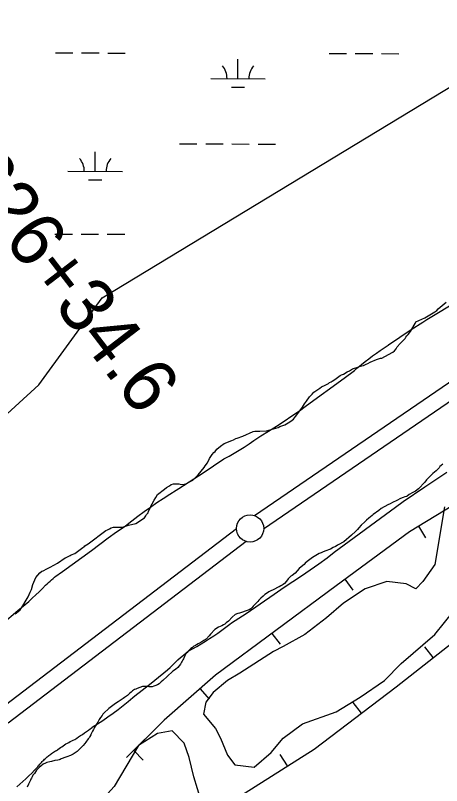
# Model space of a CAD drawing. Extents: x 3177385 to 3215275, y 903885 to 929304.
# Drawn here: x 3193361 to 3194143, y 917073 to 918487 of the extents above; entities that cross this region are included whole.
import ezdxf

# ---------------------------------------------------------------- set-up
doc = ezdxf.new("R2010")
doc.units = 0
for name, color, linetype in [('V-BORW-LINE', 7, 'Continuous'), ('V-LEVE-TOET', 7, 'Continuous'), ('V-SITE-VEGE', 7, 'Continuous'), ('V-SURV-IDEN', 7, 'Continuous'), ('V-SURV-LINE', 7, 'Continuous'), ('V-WETL-SWMP', 7, 'Continuous')]:
    doc.layers.add(name, color=color, linetype=linetype)

msp = doc.modelspace()

# ---------------------------------------------------------------- linework, layer by layer
at = {"layer": 'V-BORW-LINE'}
for p, q in [((3194100.3, 917548.6), (3194113.3, 917527.2)), ((3193965.2, 917451.3), (3193980, 917431.2)), ((3193831.4, 917352), (3193846.3, 917331.9)), ((3194127.2, 917307.4), (3194111.8, 917327)), ((3193699.6, 917250.2), (3193716.1, 917231.4)), ((3193995.5, 917205.4), (3193980.4, 917225.3)), ((3193577.9, 917136.7), (3193595.6, 917119)), ((3193860.1, 917108.6), (3193846.7, 917129.8))]:
    msp.add_line(p, q, dxfattribs=at)
for points in [[(3194274, 917653.9), (3194083.8, 917538.6)], [(3194083.8, 917538.6), (3193949.2, 917439.5)], [(3193949.2, 917439.5), (3193728.2, 917275.3)], [(3194059, 917253.6), (3194170.6, 917341.5)], [(3193728.2, 917275.3), (3193633.6, 917192.4)], [(3193909, 917139.6), (3194059, 917253.6)], [(3193633.6, 917192.4), (3193565, 917123.8)], [(3193633.6, 917192.4), (3193579, 917137.7)], [(3193770.6, 917052.1), (3193909, 917139.6)]]:
    msp.add_lwpolyline(points, dxfattribs=at)
at = {"layer": 'V-LEVE-TOET'}
for points in [[(3193416.5, 917440.6), (3193419.2, 917443.1), (3193421.8, 917445.6), (3193424.6, 917448.1), (3193427.3, 917450.5), (3193430.1, 917452.8), (3193433, 917455.1), (3193435.8, 917457.4), (3193438.8, 917459.6), (3193441.7, 917461.7), (3193444.7, 917463.8), (3193447.1, 917465.4), (3193447.1, 917465.4), (3193500.4, 917504.3), (3193500.4, 917504.3), (3193515.6, 917515.9), (3193531, 917527.2), (3193546.5, 917538.3), (3193562.3, 917549.1), (3193563.2, 917549.6), (3193563.2, 917549.6), (3193574.3, 917558.5), (3193585.6, 917567.1), (3193597, 917575.6), (3193608.5, 917583.9), (3193620.2, 917592), (3193632.1, 917599.8), (3193644, 917607.5), (3193656.1, 917614.9), (3193660.7, 917617.7), (3193660.7, 917617.7), (3193705.4, 917646.8), (3193743.4, 917672.4), (3193743.4, 917672.4), (3193752.8, 917677.5), (3193762.2, 917682.9), (3193771.4, 917688.4), (3193780.5, 917694), (3193789.5, 917699.9), (3193798.5, 917705.8), (3193807.3, 917712), (3193811, 917714.6), (3193825.4, 917723.4), (3193839.7, 917732.4), (3193853.9, 917741.6), (3193868, 917751.1), (3193881.8, 917760.7), (3193895, 917770.3), (3193963.8, 917820.7), (3193982.6, 917834.4), (3193989.1, 917840), (3193995.7, 917845.5), (3194002.4, 917851), (3194009.2, 917856.3), (3194016.1, 917861.5), (3194023.1, 917866.6), (3194030.1, 917871.5), (3194037.2, 917876.4), (3194044.5, 917881.1), (3194045, 917881.5), (3194065.8, 917895.9), (3194086.8, 917909.9), (3194108.1, 917923.6), (3194115.8, 917928.4), (3194115.8, 917928.4), (3194175.4, 917964.6)], [(3193441.1, 917140.4), (3193443.6, 917142.2), (3193446.1, 917143.9), (3193448.6, 917145.6), (3193451.2, 917147.3), (3193453.7, 917148.9), (3193456.4, 917150.4), (3193459, 917151.9), (3193461.7, 917153.4), (3193464.4, 917154.8), (3193467.1, 917156.1), (3193469.7, 917157.4), (3193473.4, 917159.6), (3193477, 917161.9), (3193480.6, 917164.3), (3193484.2, 917166.6), (3193487.8, 917169.1), (3193491.3, 917171.6), (3193494.8, 917174.1), (3193498.2, 917176.7), (3193501.6, 917179.4), (3193501.7, 917179.5), (3193511.5, 917185.8), (3193521.1, 917192.2), (3193530.7, 917198.8), (3193540.1, 917205.6), (3193549.4, 917212.5), (3193558.6, 917219.6), (3193567.6, 917226.8), (3193576.6, 917234.3), (3193580.1, 917237.3), (3193580.1, 917237.3), (3193607, 917258.1), (3193633.5, 917279.3), (3193640.2, 917284.8), (3193640.2, 917284.8), (3193644.8, 917289.5), (3193649.5, 917294.2), (3193654.2, 917298.8), (3193659.1, 917303.3), (3193664, 917307.7), (3193669, 917312), (3193674.1, 917316.3), (3193677.8, 917319.2), (3193677.8, 917319.2), (3193685.8, 917323.6), (3193693.7, 917328.1), (3193701.6, 917332.7), (3193709.4, 917337.5), (3193717, 917342.4), (3193724.7, 917347.4), (3193732.2, 917352.6), (3193739.6, 917357.9), (3193746.9, 917363.3), (3193754.2, 917368.9), (3193757.6, 917371.5), (3193757.6, 917371.5), (3193783.9, 917388.5), (3193809.9, 917406), (3193835.7, 917423.9), (3193853.7, 917436.8), (3193853.7, 917436.8), (3193869.9, 917447.1), (3193885.9, 917457.6), (3193901.8, 917468.4), (3193917.4, 917479.5), (3193932.8, 917490.9), (3193945.8, 917500.8), (3193945.8, 917500.8), (3194058.2, 917583.8), (3194072, 917594.2), (3194072, 917594.2), (3194112, 917621.2), (3194152.3, 917647.8)], [(3193336.9, 917369.6), (3193365.5, 917394.1), (3193365.5, 917394.1), (3193372.2, 917399.6), (3193378.9, 917405.1), (3193385.4, 917410.8), (3193391.9, 917416.6), (3193398.2, 917422.5), (3193404.5, 917428.5), (3193410.6, 917434.6), (3193416.5, 917440.6)], [(3193363.7, 917070.3), (3193369.3, 917075.1), (3193374.9, 917080.1), (3193380.3, 917085.1), (3193385.7, 917090.2), (3193391, 917095.4), (3193396.2, 917100.7), (3193401.3, 917106.1), (3193402, 917106.9), (3193403.3, 917108.6), (3193404.6, 917110.2), (3193406, 917111.8), (3193407.4, 917113.4), (3193408.8, 917114.9), (3193410.2, 917116.5), (3193411.6, 917118), (3193413.1, 917119.4), (3193414.6, 917120.9), (3193416.1, 917122.3), (3193417.7, 917123.7), (3193419.3, 917125.1), (3193420.9, 917126.4), (3193422.5, 917127.8), (3193424.1, 917129), (3193425.8, 917130.3), (3193427.5, 917131.5), (3193429.2, 917132.7), (3193430.9, 917133.9), (3193432.7, 917135), (3193434.5, 917136.2), (3193436.2, 917137.2), (3193438.1, 917138.3), (3193438.7, 917138.6), (3193441.1, 917140.4)]]:
    msp.add_lwpolyline(points, dxfattribs=at)
at = {"layer": 'V-SITE-VEGE'}
for points in [[(3194011.9, 917849.9), (3194023.3, 917854.7), (3194030.7, 917857.4), (3194032.8, 917857.4), (3194038.2, 917860.1), (3194053, 917868.3), (3194056.3, 917871), (3194059, 917874.4), (3194061, 917877.8), (3194066.4, 917883.9), (3194075.8, 917893.4), (3194077.1, 917896.1), (3194079.1, 917898.2), (3194081.2, 917900.9), (3194085.8, 917906.3), (3194092.5, 917917.8), (3194093.9, 917921.2), (3194095.2, 917923.9), (3194112, 917931.4), (3194130.2, 917942.3), (3194133.6, 917945), (3194136.3, 917947.7), (3194151.1, 917960)], [(3193452.1, 917490.5), (3193454.1, 917491.2), (3193458.8, 917493.9), (3193461.5, 917495.2), (3193463.5, 917495.9), (3193470.3, 917498.7), (3193484.4, 917509.5), (3193487.1, 917510.9), (3193488.4, 917512.9), (3193494.5, 917516.4), (3193526.8, 917540.8), (3193530.1, 917542.2), (3193533.5, 917544.2), (3193536.9, 917545.6), (3193540.9, 917547), (3193555.8, 917547.1), (3193561.1, 917548.4), (3193568.6, 917550.5), (3193582, 917553.9), (3193597.5, 917564.2), (3193600.2, 917567.5), (3193601.5, 917570.2), (3193604.2, 917573.6), (3193604.9, 917576.3), (3193608.9, 917583.1), (3193609.6, 917585.8), (3193611.6, 917589.9), (3193615.6, 917596.7), (3193618.3, 917601.4), (3193621.6, 917606.8), (3193634.4, 917617), (3193638.4, 917619.7), (3193643.8, 917623.1), (3193646.5, 917625.2), (3193651.2, 917626.5), (3193660.7, 917626.6), (3193664.7, 917625.3), (3193670.8, 917626), (3193673.5, 917626.7), (3193676.2, 917628), (3193678.2, 917629.4), (3193680.2, 917630.1), (3193686.3, 917633.5), (3193689.6, 917636.2), (3193696.3, 917643), (3193707.1, 917656.5), (3193709.1, 917659.3), (3193713.1, 917665.4), (3193717.1, 917672.8), (3193721.8, 917680.2), (3193725.2, 917684.3), (3193727.2, 917685.7), (3193730.5, 917690.4), (3193737.2, 917695.9), (3193744, 917700.6), (3193758.1, 917706.1), (3193760.8, 917707.5), (3193765.5, 917709.5), (3193767.6, 917710.2), (3193778.3, 917714.3), (3193797.2, 917722.5), (3193799.9, 917723.2), (3193809.3, 917723.2), (3193821.5, 917724), (3193843.1, 917730.2), (3193845.8, 917731.5), (3193855.2, 917735), (3193861.2, 917738.4), (3193866, 917741.8), (3193871.3, 917745.2), (3193874.7, 917749.9), (3193877.4, 917753.3), (3193882.1, 917760.1), (3193884.7, 917762.8), (3193887.4, 917767.5), (3193891.4, 917773.6), (3193894.8, 917778.4), (3193900.1, 917786.5), (3193905.5, 917791.3), (3193908.2, 917794.6), (3193912.2, 917797.4), (3193919, 917802.1), (3193922.3, 917804.8), (3193929.1, 917807.6), (3193935.1, 917811), (3193937.1, 917812.4), (3193939.8, 917813.7), (3193941.9, 917815.1), (3193946.6, 917817.8), (3193956.7, 917825.3), (3193959.3, 917826.6), (3193962.7, 917828), (3193969.4, 917832.1), (3193973.5, 917834.1), (3193979.5, 917837.6), (3193989, 917841), (3193993.7, 917842.4), (3193999.1, 917843.7), (3194004.5, 917846.5), (3194007.2, 917847.2), (3194011.9, 917849.9)], [(3194144.8, 917662.7), (3194142, 917659.9), (3194139.6, 917658.3), (3194138, 917655.9), (3194132.4, 917650.6), (3194126.4, 917645.4), (3194114.9, 917633.7), (3194111.7, 917629.3), (3194108.5, 917626.4), (3194103.3, 917620.4), (3194100.1, 917617.2), (3194094.5, 917613.1), (3194090.1, 917610.7), (3194083.3, 917606.7), (3194079.7, 917604.2), (3194078.1, 917603), (3194075.3, 917602.6)], [(3194075.3, 917602.6), (3194072.1, 917601.4), (3194067.3, 917599.7), (3194060.5, 917595.7), (3194052.5, 917592.5), (3194048.1, 917590), (3194044.1, 917588), (3194031.7, 917581.1), (3194027.3, 917577.5), (3194017.3, 917570.2), (3194015, 917568.6), (3194012.2, 917566.2), (3194009.4, 917563.4), (3194004.6, 917559.7), (3194001.8, 917556.5), (3193995.4, 917550.4), (3193990.6, 917545.6), (3193988.2, 917542.4), (3193985, 917539.2), (3193977.4, 917532.3), (3193963.1, 917519.8), (3193953.1, 917514.5), (3193951.1, 917513.3), (3193947.9, 917511.7), (3193943.5, 917509.7), (3193938.7, 917506.8), (3193928.3, 917503.2), (3193923.9, 917501.2), (3193921.5, 917499.9), (3193917.9, 917498.7), (3193915.1, 917497.1), (3193905.9, 917491.4), (3193895.9, 917484.2), (3193892.3, 917480.9), (3193890.3, 917478.5), (3193888.3, 917476.5), (3193881.5, 917470.9), (3193877.5, 917466.8), (3193874, 917462.8), (3193868.4, 917458.4), (3193866.4, 917457.1), (3193864, 917455.1), (3193861.2, 917452.3), (3193858, 917447.9), (3193854.4, 917443.8), (3193852, 917441.8), (3193850, 917440.6), (3193847.6, 917439.4), (3193844.8, 917437.4), (3193842.8, 917436.6), (3193834.8, 917432.5), (3193828.4, 917429.7), (3193826, 917428.1), (3193823.2, 917426.4), (3193818.4, 917423.2), (3193815.2, 917420), (3193810.8, 917416.4), (3193807.3, 917412.7), (3193805.3, 917410.3), (3193797.3, 917402.2), (3193795.3, 917399.4), (3193792.5, 917397), (3193789.7, 917395.4), (3193782.5, 917392.5), (3193777.7, 917390.9), (3193773.7, 917389.7), (3193771.7, 917389.3), (3193768.9, 917388.5), (3193764.1, 917386.4), (3193758.5, 917381.6), (3193751.7, 917374.7), (3193747.7, 917371.1), (3193744.9, 917369.1), (3193742.5, 917367.9), (3193739.7, 917365.9), (3193733.7, 917363.4), (3193726.9, 917359), (3193718.6, 917350.5), (3193716.2, 917347.3), (3193711, 917341.6), (3193709, 917340), (3193706.6, 917339.2), (3193702.6, 917336.4), (3193696.2, 917332.7), (3193693, 917330.7), (3193691, 917329.9), (3193688.2, 917328.3), (3193685.8, 917326.3), (3193683, 917324.3), (3193677.8, 917319.4), (3193675.8, 917316.6), (3193673.8, 917314.6), (3193671.1, 917309.8), (3193669.1, 917305.3), (3193668.3, 917303.3), (3193666.7, 917300.9), (3193665.9, 917298.9), (3193663.5, 917295.3), (3193659.1, 917289.6), (3193654.8, 917285.6), (3193650, 917282.8)], [(3194148.2, 917584.4), (3194130.5, 917478.2), (3194108.4, 917447.2), (3194095.1, 917433.9), (3194077.4, 917442.8), (3194042.1, 917447.2), (3194002.3, 917433.9), (3193962.5, 917407.4), (3193931.5, 917380.8), (3193891.7, 917349.8), (3193851.9, 917327.7), (3193834.2, 917318.9), (3193772.3, 917279), (3193750.1, 917265.7), (3193723.6, 917243.6), (3193710.3, 917225.9), (3193705.9, 917203.8), (3193728, 917177.2), (3193736.9, 917159.5), (3193750.1, 917128.5), (3193763.4, 917110.8), (3193798.8, 917106.4), (3193829.8, 917133), (3193851.9, 917159.5), (3193887.3, 917186.1), (3193949.2, 917208.2), (3193993.4, 917234.8), (3194037.6, 917265.7), (3194068.6, 917296.7), (3194130.5, 917349.8), (3194165.9, 917394.1)], [(3193360.8, 917388.1), (3193366.2, 917392.1), (3193369.5, 917395.5), (3193374.9, 917402.3), (3193380.9, 917413.1), (3193384.3, 917419.2), (3193388.3, 917427.4), (3193390.3, 917432.8), (3193392.9, 917441.6), (3193398.3, 917454.4), (3193405.6, 917463.2), (3193409.7, 917465.9), (3193411.7, 917466.6), (3193418.4, 917470.7), (3193424.5, 917473.5), (3193438, 917480.9), (3193452.1, 917490.5)], [(3193650, 917282.8), (3193639.2, 917273.1), (3193631.6, 917265.4), (3193628.4, 917263), (3193624.4, 917259.4), (3193621.6, 917257.4), (3193616.8, 917255.7), (3193614.8, 917254.9), (3193611.6, 917254.1), (3193606, 917253.7), (3193602.4, 917254.5), (3193594, 917254.4), (3193584.4, 917250.8), (3193582, 917249.5), (3193579.6, 917248.7), (3193575.6, 917246.3), (3193573.6, 917244.3), (3193570, 917241.5), (3193566.4, 917238.2), (3193564.8, 917236.6), (3193561.2, 917234.2), (3193558.4, 917232.6), (3193553.2, 917228.9), (3193551.6, 917227.7), (3193549.6, 917226.5), (3193544.8, 917223.3), (3193539.6, 917219.6), (3193532.4, 917214), (3193523.2, 917205.5), (3193521.3, 917203.5), (3193520.1, 917201.5), (3193516.9, 917197.5), (3193514.9, 917193.9), (3193513.3, 917191.4), (3193512.1, 917189), (3193507.7, 917182.2), (3193505.3, 917178.2), (3193504.2, 917175.4), (3193502.2, 917172.5), (3193501, 917169.7), (3193499.8, 917167.7), (3193499.4, 917165.7), (3193497.4, 917162.9), (3193496.6, 917160.9), (3193494.6, 917158.5), (3193490.2, 917152), (3193488.3, 917150), (3193485.5, 917146.4), (3193482.3, 917142.8), (3193474.3, 917135.1), (3193468.7, 917131.5), (3193467.1, 917130.2), (3193462.3, 917127.8), (3193455.5, 917125.4), (3193451.5, 917124.2), (3193446.7, 917122.1), (3193444.7, 917121.7), (3193443.1, 917120.5), (3193441.1, 917120.1), (3193438.7, 917119.3), (3193433.1, 917118.4), (3193427.1, 917116.8), (3193424.3, 917116.4), (3193418.7, 917115.2), (3193416.3, 917113.9), (3193411.9, 917111.9), (3193407.5, 917108.3), (3193405.5, 917106.3), (3193403.1, 917104.6), (3193399.9, 917101), (3193395.9, 917095), (3193393.1, 917091.4), (3193391.5, 917088.5), (3193390.3, 917086.1), (3193389.2, 917084.5), (3193388.4, 917082.5), (3193387.6, 917080.1), (3193386.4, 917077.7), (3193384.8, 917075.3), (3193382.4, 917069.7)], [(3193299, 916646.1), (3193365.3, 916725.8), (3193471.5, 916818.7), (3193537.8, 916885.1), (3193599.8, 916951.5), (3193657.3, 917009), (3193701.5, 917044.4), (3193688.2, 917088.7), (3193679.4, 917124.1), (3193670.5, 917150.7), (3193648.4, 917172.8), (3193621.9, 917168.4), (3193586.5, 917146.2), (3193542.2, 917071), (3193493.6, 917017.9), (3193458.2, 917004.6), (3193400.7, 916933.8), (3193352.1, 916911.7)]]:
    msp.add_lwpolyline(points, dxfattribs=at)
at = {"layer": 'V-SURV-LINE'}
for points in [[(3193799.3, 917568.3), (3195475.5, 918716.7)], [(3195492.4, 918691.9), (3193816.2, 917543.6)], [(3193329.5, 917210.9), (3193766.3, 917544.5)], [(3193784.5, 917520.6), (3193347.7, 917187)]]:
    msp.add_lwpolyline(points, dxfattribs=at)
msp.add_circle((3193791.3, 917544.7), 25, dxfattribs=at)
at = {"layer": 'V-WETL-SWMP'}
for p, q in [((3193434.4, 918417.7), (3193466.4, 918417.7)), ((3193482.4, 918417.6), (3193514.4, 918417.6)), ((3193530.4, 918417.5), (3193562.4, 918417.4)), ((3193769.2, 918370.5), (3193769.2, 918406.5)), ((3193936.3, 918416.6), (3193968.3, 918416.5)), ((3193984.3, 918416.5), (3194016.3, 918416.4)), ((3194032.3, 918416.4), (3194064.3, 918416.3)), ((3193719.2, 918370.7), (3193819.2, 918370.4)), ((3193757.1, 918355.1), (3193781.1, 918355.1)), ((3193662, 918250.7), (3193694, 918250.6)), ((3193710, 918250.6), (3193742, 918250.5)), ((3193758, 918250.5), (3193790, 918250.4)), ((3193806, 918250.4), (3193838, 918250.3)), ((3193507.3, 918200.3), (3193507.4, 918236.3)), ((3193457.3, 918200.4), (3193557.3, 918200.2)), ((3193495.3, 918184.9), (3193519.3, 918184.9)), ((3193433.6, 918085.1), (3193465.6, 918085)), ((3193481.6, 918085), (3193513.6, 918084.9)), ((3193529.6, 918084.8), (3193561.6, 918084.8))]:
    msp.add_line(p, q, dxfattribs=at)
msp.add_lwpolyline([(3187662.9, 916111.3), (3187822.4, 915951.7), (3187967.4, 915835.7), (3188083.4, 915777.7), (3188315.3, 915690.6), (3188764.8, 915574.6), (3189069.2, 915545.6), (3189417.1, 915502.1), (3189750.6, 915502.1), (3190185.5, 915516.6), (3190591.4, 915690.6), (3191127.8, 915922.7), (3191490.3, 916241.8), (3192099.2, 916720.5), (3192273.1, 916764), (3192389.1, 916836.6), (3192679.1, 917126.7), (3192809.5, 917286.3), (3192969, 917460.3), (3193230, 917648.9), (3193403.9, 917808.5), (3193519.9, 917968), (3194390.4, 918496.3)], dxfattribs=at)
for centre, start, end in [((3193713.9, 918371.1), 359.0948, 40.6385), ((3193824.4, 918370.9), 139.0948, 180.6385), ((3193452.1, 918200.9), 359.0948, 40.6385), ((3193562.6, 918200.7), 139.0948, 180.6385)]:
    msp.add_arc(centre, 35.2, start, end, dxfattribs=at)

# ---------------------------------------------------------------- texts
at = {"layer": 'V-SURV-IDEN'}
msp.add_text('626+34.6', height=100, rotation=307.5108, dxfattribs=at).set_placement((3193247, 918193.5))

doc.saveas('drawing.dxf')
